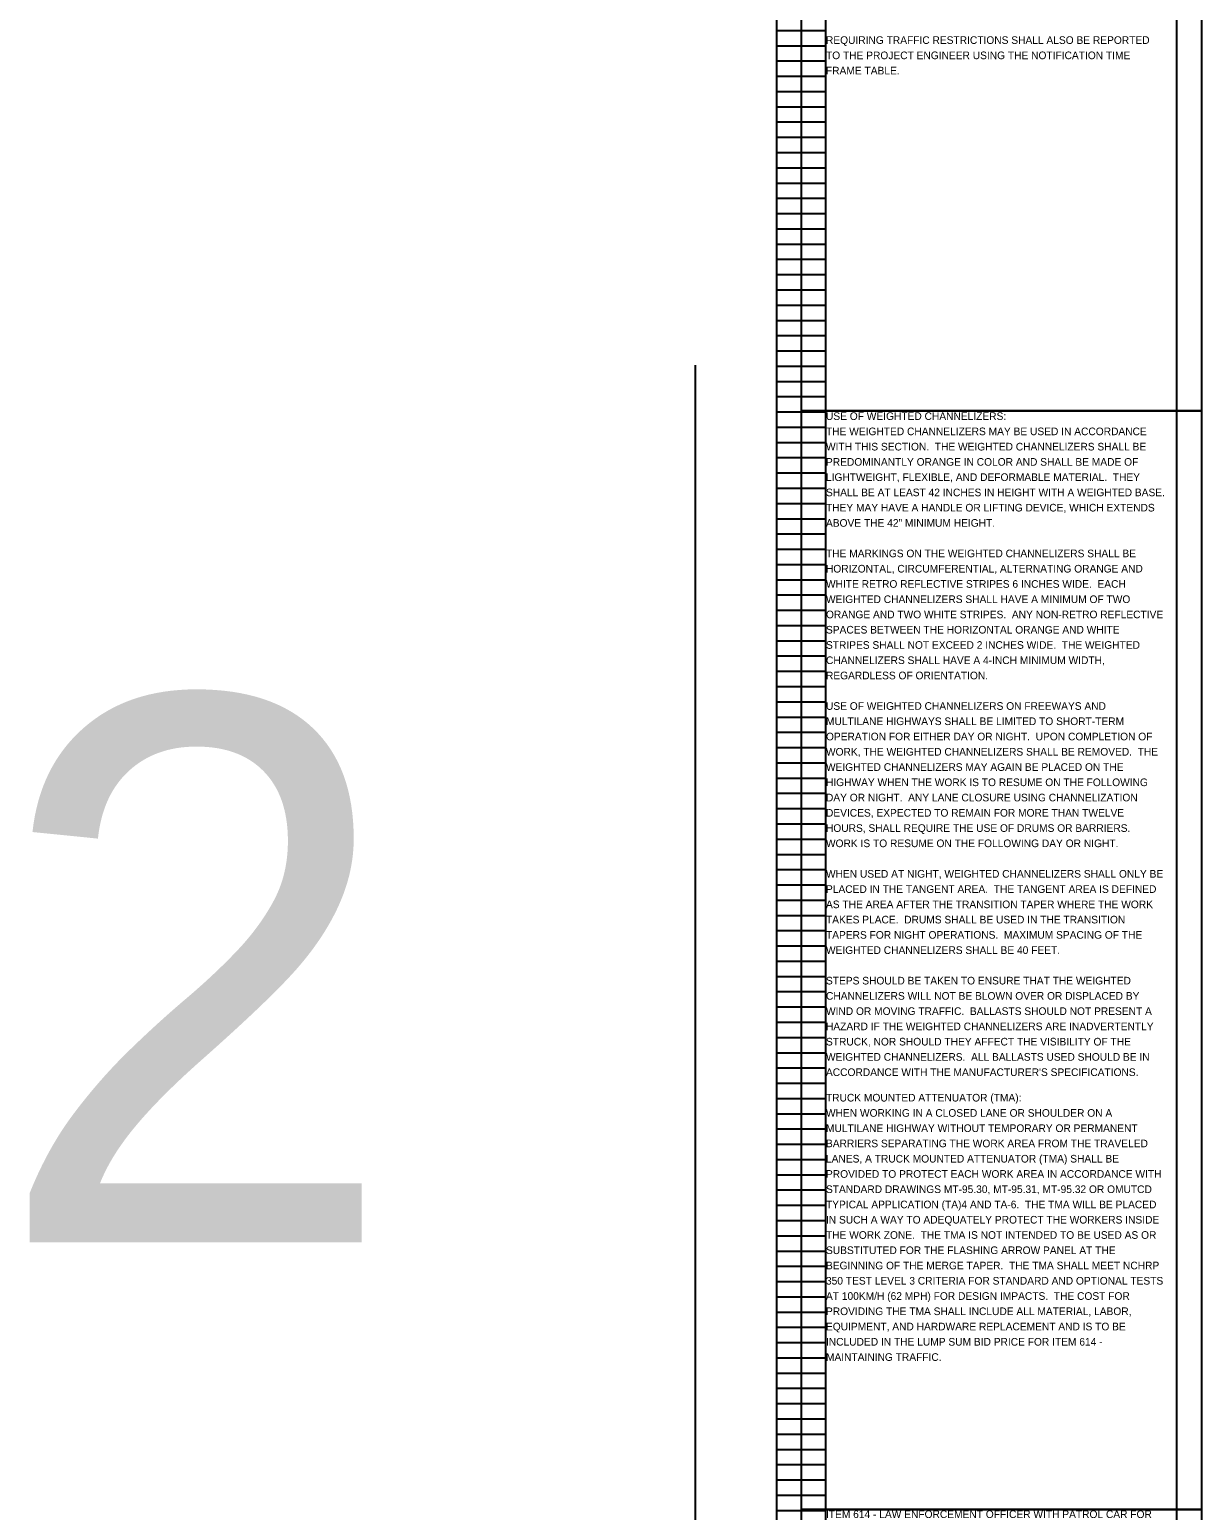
# Model space of a CAD drawing. Extents: x -13 to 322, y -402 to 112.
# Drawn here: x 32.42 to 53.92, y -79.66 to -52.48 of the extents above; entities that cross this region are included whole.
import ezdxf

# ---------------------------------------------------------------- set-up
doc = ezdxf.new("R2010")
doc.units = 0
doc.layers.add('SC_Scratch1', color=7, linetype='Continuous')
doc.layers.add('SH_Text', color=7, linetype='Continuous')

msp = doc.modelspace()

# ---------------------------------------------------------------- linework, layer by layer
at = {"layer": 'SC_Scratch1'}
for p, q in [((46.134, -59.5), (46.134, -39.34)), ((47.034, -59.5), (47.034, -39.34)), ((53.474, -59.5), (53.474, -39.34)), ((46.134, -52.5), (47.034, -52.5)), ((46.134, -52.78), (47.034, -52.78)), ((46.134, -53.06), (47.034, -53.06)), ((46.134, -53.34), (47.034, -53.34)), ((46.134, -53.62), (47.034, -53.62)), ((46.134, -53.9), (47.034, -53.9)), ((46.134, -54.18), (47.034, -54.18)), ((46.134, -54.46), (47.034, -54.46)), ((46.134, -54.74), (47.034, -54.74)), ((46.134, -55.02), (47.034, -55.02)), ((46.134, -55.3), (47.034, -55.3)), ((46.134, -55.58), (47.034, -55.58)), ((46.134, -55.86), (47.034, -55.86)), ((46.134, -56.14), (47.034, -56.14)), ((46.134, -56.42), (47.034, -56.42)), ((46.134, -56.7), (47.034, -56.7)), ((46.134, -56.98), (47.034, -56.98)), ((46.134, -57.26), (47.034, -57.26)), ((46.134, -57.54), (47.034, -57.54)), ((46.134, -57.82), (47.034, -57.82)), ((46.134, -58.1), (47.034, -58.1)), ((46.134, -58.38), (47.034, -58.38)), ((44.634, -58.64), (44.634, -80.64)), ((46.134, -58.66), (47.034, -58.66)), ((46.134, -58.94), (47.034, -58.94)), ((46.134, -59.22), (47.034, -59.22)), ((46.134, -59.5), (47.034, -59.5)), ((46.134, -59.5), (47.034, -59.5)), ((46.134, -79.66), (46.134, -59.5)), ((47.034, -79.66), (47.034, -59.5)), ((53.474, -79.66), (53.474, -59.5)), ((46.134, -59.78), (47.034, -59.78)), ((46.134, -60.06), (47.034, -60.06)), ((46.134, -60.34), (47.034, -60.34)), ((46.134, -60.62), (47.034, -60.62)), ((46.134, -60.9), (47.034, -60.9)), ((46.134, -61.18), (47.034, -61.18)), ((46.134, -61.46), (47.034, -61.46)), ((46.134, -61.74), (47.034, -61.74)), ((46.134, -62.02), (47.034, -62.02)), ((46.134, -62.3), (47.034, -62.3)), ((46.134, -62.58), (47.034, -62.58)), ((46.134, -62.86), (47.034, -62.86)), ((46.134, -63.14), (47.034, -63.14)), ((46.134, -63.42), (47.034, -63.42)), ((46.134, -63.7), (47.034, -63.7)), ((46.134, -63.98), (47.034, -63.98)), ((46.134, -64.26), (47.034, -64.26)), ((46.134, -64.54), (47.034, -64.54)), ((46.134, -64.82), (47.034, -64.82)), ((46.134, -65.1), (47.034, -65.1)), ((46.134, -65.38), (47.034, -65.38)), ((46.134, -65.66), (47.034, -65.66)), ((46.134, -65.94), (47.034, -65.94)), ((46.134, -66.22), (47.034, -66.22)), ((46.134, -66.5), (47.034, -66.5)), ((46.134, -66.78), (47.034, -66.78)), ((46.134, -67.06), (47.034, -67.06)), ((46.134, -67.34), (47.034, -67.34)), ((46.134, -67.62), (47.034, -67.62)), ((46.134, -67.9), (47.034, -67.9)), ((46.134, -68.18), (47.034, -68.18)), ((46.134, -68.46), (47.034, -68.46)), ((46.134, -68.74), (47.034, -68.74)), ((46.134, -69.02), (47.034, -69.02)), ((46.134, -69.3), (47.034, -69.3)), ((46.134, -69.58), (47.034, -69.58)), ((46.134, -69.86), (47.034, -69.86)), ((46.134, -70.14), (47.034, -70.14)), ((46.134, -70.42), (47.034, -70.42)), ((46.134, -70.7), (47.034, -70.7)), ((46.134, -70.98), (47.034, -70.98)), ((46.134, -71.26), (47.034, -71.26)), ((46.134, -71.54), (47.034, -71.54)), ((46.134, -71.82), (47.034, -71.82)), ((46.134, -72.1), (47.034, -72.1)), ((46.134, -72.38), (47.034, -72.38)), ((46.134, -72.66), (47.034, -72.66)), ((46.134, -72.94), (47.034, -72.94)), ((46.134, -73.22), (47.034, -73.22)), ((46.134, -73.5), (47.034, -73.5)), ((46.134, -73.78), (47.034, -73.78)), ((46.134, -74.06), (47.034, -74.06)), ((46.134, -74.34), (47.034, -74.34)), ((46.134, -74.62), (47.034, -74.62)), ((46.134, -74.9), (47.034, -74.9)), ((46.134, -75.18), (47.034, -75.18)), ((46.134, -75.46), (47.034, -75.46)), ((46.134, -75.74), (47.034, -75.74)), ((46.134, -76.02), (47.034, -76.02)), ((46.134, -76.3), (47.034, -76.3)), ((46.134, -76.58), (47.034, -76.58)), ((46.134, -76.86), (47.034, -76.86)), ((46.134, -77.14), (47.034, -77.14)), ((46.134, -77.42), (47.034, -77.42)), ((46.134, -77.7), (47.034, -77.7)), ((46.134, -77.98), (47.034, -77.98)), ((46.134, -78.26), (47.034, -78.26)), ((46.134, -78.54), (47.034, -78.54)), ((46.134, -78.82), (47.034, -78.82)), ((46.134, -79.1), (47.034, -79.1)), ((46.134, -79.38), (47.034, -79.38)), ((46.134, -79.66), (47.034, -79.66)), ((46.134, -79.66), (47.034, -79.66)), ((46.134, -99.82), (46.134, -79.66)), ((47.034, -99.82), (47.034, -79.66)), ((53.474, -99.82), (53.474, -79.66))]:
    msp.add_line(p, q, dxfattribs=at)
for points in [[(46.584, -39.323), (53.924, -39.323), (53.924, -59.483), (46.584, -59.483)], [(46.584, -59.483), (53.924, -59.483), (53.924, -79.643), (46.584, -79.643)], [(46.584, -79.643), (53.924, -79.643), (53.924, -99.803), (46.584, -99.803)]]:
    msp.add_lwpolyline(points, close=True, dxfattribs=at)

# ---------------------------------------------------------------- texts
at = {"layer": 'SH_Text'}
for s, height, p in [('REQUIRING TRAFFIC RESTRICTIONS SHALL ALSO BE REPORTED ', 0.14, (47.034, -52.747)), ('TO THE PROJECT ENGINEER USING THE NOTIFICATION TIME ', 0.14, (47.034, -53.027)), ('FRAME TABLE. ', 0.14, (47.034, -53.307)), ('USE OF WEIGHTED CHANNELIZERS:', 0.14, (47.034, -59.648)), ('THE WEIGHTED CHANNELIZERS MAY BE USED IN ACCORDANCE ', 0.14, (47.034, -59.928)), ('WITH THIS SECTION.  THE WEIGHTED CHANNELIZERS SHALL BE ', 0.14, (47.034, -60.208)), ('PREDOMINANTLY ORANGE IN COLOR AND SHALL BE MADE OF ', 0.14, (47.034, -60.488)), ('LIGHTWEIGHT, FLEXIBLE, AND DEFORMABLE MATERIAL.  THEY ', 0.14, (47.034, -60.768)), ('SHALL BE AT LEAST 42 INCHES IN HEIGHT WITH A WEIGHTED BASE.  ', 0.14, (47.034, -61.048)), ('THEY MAY HAVE A HANDLE OR LIFTING DEVICE, WHICH EXTENDS ', 0.14, (47.034, -61.328)), ('ABOVE THE 42" MINIMUM HEIGHT.', 0.14, (47.034, -61.608)), ('THE MARKINGS ON THE WEIGHTED CHANNELIZERS SHALL BE ', 0.14, (47.034, -62.168)), ('HORIZONTAL, CIRCUMFERENTIAL, ALTERNATING ORANGE AND ', 0.14, (47.034, -62.448)), ('WHITE RETRO REFLECTIVE STRIPES 6 INCHES WIDE.  EACH ', 0.14, (47.034, -62.728)), ('WEIGHTED CHANNELIZERS SHALL HAVE A MINIMUM OF TWO ', 0.14, (47.034, -63.008)), ('ORANGE AND TWO WHITE STRIPES.  ANY NON-RETRO REFLECTIVE ', 0.14, (47.034, -63.288)), ('SPACES BETWEEN THE HORIZONTAL ORANGE AND WHITE ', 0.14, (47.034, -63.568)), ('STRIPES SHALL NOT EXCEED 2 INCHES WIDE.  THE WEIGHTED ', 0.14, (47.034, -63.848)), ('CHANNELIZERS SHALL HAVE A 4-INCH MINIMUM WIDTH, ', 0.14, (47.034, -64.128)), ('REGARDLESS OF ORIENTATION.', 0.14, (47.034, -64.408)), ('2', 10, (31.746, -74.741)), ('USE OF WEIGHTED CHANNELIZERS ON FREEWAYS AND ', 0.14, (47.034, -64.968)), ('MULTILANE HIGHWAYS SHALL BE LIMITED TO SHORT-TERM ', 0.14, (47.034, -65.248)), ('OPERATION FOR EITHER DAY OR NIGHT.  UPON COMPLETION OF ', 0.14, (47.034, -65.528)), ('WORK, THE WEIGHTED CHANNELIZERS SHALL BE REMOVED.  THE ', 0.14, (47.034, -65.808)), ('WEIGHTED CHANNELIZERS MAY AGAIN BE PLACED ON THE ', 0.14, (47.034, -66.088)), ('HIGHWAY WHEN THE WORK IS TO RESUME ON THE FOLLOWING ', 0.14, (47.034, -66.368)), ('DAY OR NIGHT.  ANY LANE CLOSURE USING CHANNELIZATION ', 0.14, (47.034, -66.648)), ('DEVICES, EXPECTED TO REMAIN FOR MORE THAN TWELVE ', 0.14, (47.034, -66.928)), ('HOURS, SHALL REQUIRE THE USE OF DRUMS OR BARRIERS.  ', 0.14, (47.034, -67.208)), ('WORK IS TO RESUME ON THE FOLLOWING DAY OR NIGHT.', 0.14, (47.034, -67.488)), ('WHEN USED AT NIGHT, WEIGHTED CHANNELIZERS SHALL ONLY BE ', 0.14, (47.034, -68.048)), ('PLACED IN THE TANGENT AREA.  THE TANGENT AREA IS DEFINED ', 0.14, (47.034, -68.328)), ('AS THE AREA AFTER THE TRANSITION TAPER WHERE THE WORK ', 0.14, (47.034, -68.608)), ('TAKES PLACE.  DRUMS SHALL BE USED IN THE TRANSITION ', 0.14, (47.034, -68.888)), ('TAPERS FOR NIGHT OPERATIONS.  MAXIMUM SPACING OF THE ', 0.14, (47.034, -69.168)), ('WEIGHTED CHANNELIZERS SHALL BE 40 FEET.', 0.14, (47.034, -69.448)), ('STEPS SHOULD BE TAKEN TO ENSURE THAT THE WEIGHTED ', 0.14, (47.034, -70.008)), ('CHANNELIZERS WILL NOT BE BLOWN OVER OR DISPLACED BY ', 0.14, (47.034, -70.288)), ('WIND OR MOVING TRAFFIC.  BALLASTS SHOULD NOT PRESENT A ', 0.14, (47.034, -70.568)), ('HAZARD IF THE WEIGHTED CHANNELIZERS ARE INADVERTENTLY ', 0.14, (47.034, -70.848)), ('STRUCK, NOR SHOULD THEY AFFECT THE VISIBILITY OF THE ', 0.14, (47.034, -71.128)), ('WEIGHTED CHANNELIZERS.  ALL BALLASTS USED SHOULD BE IN ', 0.14, (47.034, -71.408)), ("ACCORDANCE WITH THE MANUFACTURER'S SPECIFICATIONS.", 0.14, (47.034, -71.688)), ('TRUCK MOUNTED ATTENUATOR (TMA):', 0.14, (47.034, -72.156)), ('WHEN WORKING IN A CLOSED LANE OR SHOULDER ON A ', 0.14, (47.034, -72.436)), ('MULTILANE HIGHWAY WITHOUT TEMPORARY OR PERMANENT ', 0.14, (47.034, -72.716)), ('BARRIERS SEPARATING THE WORK AREA FROM THE TRAVELED ', 0.14, (47.034, -72.996)), ('LANES, A TRUCK MOUNTED ATTENUATOR (TMA) SHALL BE ', 0.14, (47.034, -73.276)), ('PROVIDED TO PROTECT EACH WORK AREA IN ACCORDANCE WITH ', 0.14, (47.034, -73.556)), ('STANDARD DRAWINGS MT-95.30, MT-95.31, MT-95.32 OR OMUTCD ', 0.14, (47.034, -73.836)), ('TYPICAL APPLICATION (TA)4 AND TA-6.  THE TMA WILL BE PLACED ', 0.14, (47.034, -74.116)), ('IN SUCH A WAY TO ADEQUATELY PROTECT THE WORKERS INSIDE ', 0.14, (47.034, -74.396)), ('THE WORK ZONE.  THE TMA IS NOT INTENDED TO BE USED AS OR ', 0.14, (47.034, -74.676)), ('SUBSTITUTED FOR THE FLASHING ARROW PANEL AT THE ', 0.14, (47.034, -74.956)), ('BEGINNING OF THE MERGE TAPER.  THE TMA SHALL MEET NCHRP ', 0.14, (47.034, -75.236)), ('350 TEST LEVEL 3 CRITERIA FOR STANDARD AND OPTIONAL TESTS ', 0.14, (47.034, -75.516)), ('AT 100KM/H (62 MPH) FOR DESIGN IMPACTS.  THE COST FOR ', 0.14, (47.034, -75.796)), ('PROVIDING THE TMA SHALL INCLUDE ALL MATERIAL, LABOR, ', 0.14, (47.034, -76.076)), ('EQUIPMENT, AND HARDWARE REPLACEMENT AND IS TO BE ', 0.14, (47.034, -76.356)), ('INCLUDED IN THE LUMP SUM BID PRICE FOR ITEM 614 - ', 0.14, (47.034, -76.636)), ('MAINTAINING TRAFFIC.', 0.14, (47.034, -76.916)), ('ITEM 614 - LAW ENFORCEMENT OFFICER WITH PATROL CAR FOR ', 0.14, (47.034, -79.8))]:
    msp.add_text(s, height=height, dxfattribs=at).set_placement(p)

doc.saveas('drawing.dxf')
